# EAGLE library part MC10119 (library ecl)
Dual 2-wide 3-input "or-and" Gate
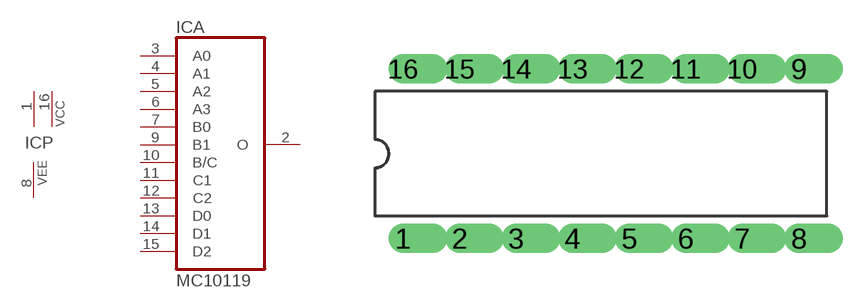
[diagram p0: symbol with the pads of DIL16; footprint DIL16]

Designator prefix IC; gates A=MC10119 P=2VCC1VEE

## MC10119  [DIL16]
1  P:VCC  pwr
2  A:O  out
3  A:A0  in
4  A:A1  in
5  A:A2  in
6  A:A3  in
7  A:B0  in
8  P:VEE  pwr
9  A:B1  in
10  A:B/C  in
11  A:C1  in
12  A:C2  in
13  A:D0  in
14  A:D1  in
15  A:D2  in
16  P:VCC  pwr

## Footprint DIL16 (pad centres in mm)
drill 0.813 offset: 1 -8.89,-3.81; 2 -6.35,-3.81; 3 -3.81,-3.81; 4 -1.27,-3.81; 5 1.27,-3.81; 6 3.81,-3.81; 7 6.35,-3.81; 8 8.89,-3.81; 9 8.89,3.81; 10 6.35,3.81; 11 3.81,3.81; 12 1.27,3.81; 13 -1.27,3.81; 14 -3.81,3.81; 15 -6.35,3.81; 16 -8.89,3.81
